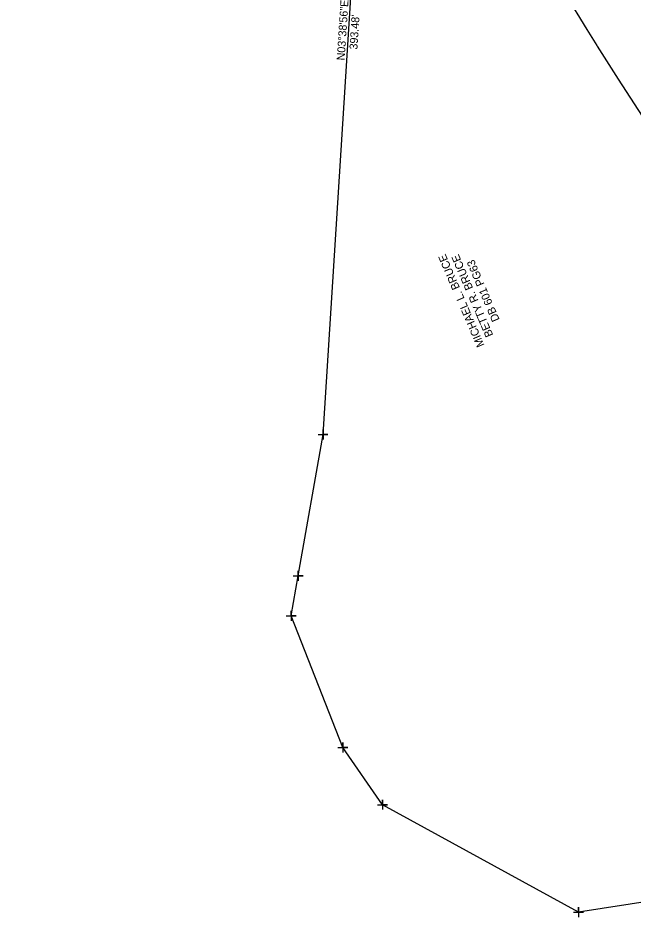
# Model space of a CAD drawing. Extents: x 1550153 to 1552579, y 809637 to 812160.
# Drawn here: x 1551716.6 to 1552025.7, y 809834 to 810285.6 of the extents above; entities that cross this region are included whole.
import ezdxf

# ---------------------------------------------------------------- set-up
doc = ezdxf.new("R2010")
doc.units = 0
for name, color, linetype in [('Exist DTM Crownline', 7, 'Continuous'), ('Exist Property Corner CELL', 7, 'Continuous'), ('Exist Property Line', 7, 'Continuous'), ('Exist Property Line Text', 7, 'Continuous'), ('Exist Property Text', 7, 'Continuous'), ('Exist Right of Way Line', 7, 'Continuous'), ('Exist Roads EOP', 7, 'Continuous')]:
    doc.layers.add(name, color=color, linetype=linetype)

msp = doc.modelspace()

# ---------------------------------------------------------------- linework, layer by layer
at = {"layer": 'Exist DTM Crownline'}
msp.add_open_spline([(1551879.82, 810614.22), (1551884.05, 810605.39), (1551895.17, 810581.82), (1551913.83, 810543.92), (1551935.88, 810500.73), (1551958.31, 810458.41), (1551980.95, 810417.48), (1552003.45, 810377.54), (1552026.55, 810337.94), (1552050.88, 810298.4), (1552075.94, 810258.8), (1552101.84, 810219.91), (1552127.91, 810181.93), (1552154.01, 810145.21), (1552180.08, 810109.84), (1552206.53, 810074.71), (1552233.39, 810039.85), (1552251.62, 810016.53), (1552260.85, 810005.29)], degree=3, dxfattribs=at)
msp.add_open_spline([(1551879.82, 810614.22), (1551884.05, 810605.39), (1551895.17, 810581.82), (1551913.83, 810543.92), (1551935.88, 810500.73), (1551958.31, 810458.41), (1551980.95, 810417.48), (1552003.45, 810377.54), (1552026.55, 810337.94), (1552050.88, 810298.4), (1552075.94, 810258.8), (1552101.84, 810219.91), (1552127.91, 810181.93), (1552154.01, 810145.21), (1552180.08, 810109.84), (1552206.53, 810074.71), (1552233.39, 810039.85), (1552251.62, 810016.53), (1552260.85, 810005.29)], degree=3, dxfattribs=at)
at = {"layer": 'Exist Property Corner CELL'}
for p, q in [((1551869.88, 810076.38), (1551869.88, 810076.38)), ((1551857.38, 810005.47), (1551857.38, 810005.47)), ((1551853.84, 809985.38), (1551853.84, 809985.38)), ((1551879.87, 809919.12), (1551879.87, 809919.12)), ((1551899.73, 809890.46), (1551899.73, 809890.46)), ((1551998.3, 809836.53), (1551998.3, 809836.53))]:
    msp.add_line(p, q, dxfattribs=at)
for points in [[(1551867.38, 810076.38), (1551872.38, 810076.38), (1551869.88, 810076.38), (1551869.88, 810078.88), (1551869.88, 810073.88)], [(1551854.88, 810005.47), (1551859.88, 810005.47), (1551857.38, 810005.47), (1551857.38, 810007.97), (1551857.38, 810002.97)], [(1551851.34, 809985.38), (1551856.34, 809985.38), (1551853.84, 809985.38), (1551853.84, 809987.88), (1551853.84, 809982.88)], [(1551877.37, 809919.12), (1551882.37, 809919.12), (1551879.87, 809919.12), (1551879.87, 809921.62), (1551879.87, 809916.62)], [(1551897.23, 809890.46), (1551902.23, 809890.46), (1551899.73, 809890.46), (1551899.73, 809892.96), (1551899.73, 809887.96)], [(1551995.8, 809836.53), (1552000.8, 809836.53), (1551998.3, 809836.53), (1551998.3, 809839.03), (1551998.3, 809834.03)]]:
    msp.add_lwpolyline(points, dxfattribs=at)
at = {"layer": 'Exist Property Line'}
for p, q in [((1551869.88, 810076.38), (1551894.92, 810469.06)), ((1551857.38, 810005.47), (1551869.88, 810076.38)), ((1551853.84, 809985.38), (1551857.38, 810005.47)), ((1551879.87, 809919.12), (1551853.84, 809985.38)), ((1551899.73, 809890.46), (1551879.87, 809919.12)), ((1551998.3, 809836.53), (1551899.73, 809890.46)), ((1552055.49, 809845.39), (1551998.3, 809836.53))]:
    msp.add_line(p, q, dxfattribs=at)
at = {"layer": 'Exist Right of Way Line'}
msp.add_lwpolyline([(1552007.43, 810271.78), (1552007.62, 810271.47), (1552018.23, 810254.88), (1552018.25, 810254.86)], dxfattribs=at)
for centre, radius, start, end in [((1544245.55, 819324.92), 11626.16, 307.933611, 310.911902), ((1554685.69, 811929.93), 3150, 206.2071, 211.76221), ((1554670.24, 811954.69), 3150, 212.65834, 221.20382)]:
    msp.add_arc(centre, radius, start, end, dxfattribs=at)
at = {"layer": 'Exist Roads EOP'}
for points in [[(1552269.13, 810011.86), (1552259.93, 810023.16), (1552240.78, 810045.4), (1552214.35, 810080.42), (1552187.88, 810115.33), (1552162.14, 810151.01), (1552135.65, 810187.58), (1552109.73, 810225.45), (1552084.16, 810264.07), (1552058.92, 810303.06), (1552035.07, 810342.61), (1552011.65, 810381.94), (1551989.05, 810421.66), (1551966.76, 810462.54), (1551944.71, 810504.82), (1551922.39, 810547.43), (1551904.23, 810585.99), (1551891.95, 810609.53), (1551888.02, 810619.12)], [(1552269.13, 810011.86), (1552259.93, 810023.16), (1552240.78, 810045.4), (1552214.35, 810080.42), (1552187.88, 810115.33), (1552162.14, 810151.01), (1552135.65, 810187.58), (1552109.73, 810225.45), (1552084.16, 810264.07), (1552058.92, 810303.06), (1552035.07, 810342.61), (1552011.65, 810381.94), (1551989.05, 810421.66), (1551966.76, 810462.54), (1551944.71, 810504.82), (1551922.39, 810547.43), (1551904.23, 810585.99), (1551891.95, 810609.53), (1551888.02, 810619.12)], [(1552253.42, 809998.9), (1552244.08, 810010.36), (1552226.02, 810034.01), (1552199.09, 810069.05), (1552172.75, 810104.35), (1552146.51, 810139.68), (1552120.18, 810176.35), (1552094.25, 810214.54), (1552068.09, 810253.47), (1552042.85, 810293.18), (1552018.16, 810332.74), (1551995.33, 810372.57), (1551972.36, 810412.53), (1551950.07, 810453.8), (1551927.46, 810496.24), (1551905.63, 810539.48), (1551886.95, 810576.34), (1551876.35, 810599.18), (1551872.14, 810607.04)], [(1552253.42, 809998.9), (1552244.08, 810010.36), (1552226.02, 810034.01), (1552199.09, 810069.05), (1552172.75, 810104.35), (1552146.51, 810139.68), (1552120.18, 810176.35), (1552094.25, 810214.54), (1552068.09, 810253.47), (1552042.85, 810293.18), (1552018.16, 810332.74), (1551995.33, 810372.57), (1551972.36, 810412.53), (1551950.07, 810453.8), (1551927.46, 810496.24), (1551905.63, 810539.48), (1551886.95, 810576.34), (1551876.35, 810599.18), (1551872.14, 810607.04)]]:
    msp.add_open_spline(points, degree=3, dxfattribs=at)

# ---------------------------------------------------------------- texts
at = {"layer": 'Exist Property Line Text'}
for s, p in [('N03°38\'56"E', (1551880.76, 810264.21)), ("393.48'", (1551887.14, 810269.68))]:
    msp.add_text(s, height=4.02, rotation=86.3511, dxfattribs=at).set_placement(p)
at = {"layer": 'Exist Property Text'}
for s, p in [('MICHAEL L. BRUCE', (1551951.08, 810121.28)), ('BETTY R. BRUCE', (1551955.48, 810126.33)), ('DB 601 PG63', (1551958.72, 810134.08))]:
    msp.add_text(s, height=4.02, rotation=113.1736, dxfattribs=at).set_placement(p)

doc.saveas('drawing.dxf')
